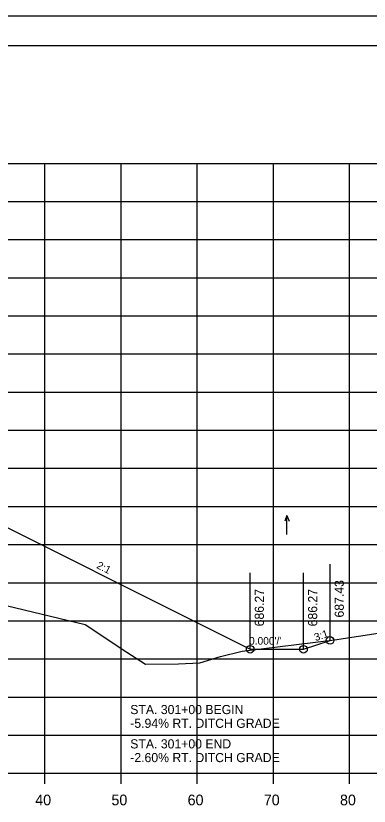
# Model space of a CAD drawing. Extents: x 1370515 to 1370849, y 383299 to 386073.
# Drawn here: x 1370714 to 1370760.4, y 383622.4 to 383726.1 of the extents above; entities that cross this region are included whole.
import ezdxf

# ---------------------------------------------------------------- set-up
doc = ezdxf.new("R2010")
doc.units = 0
for name, color, linetype in [('R_Axis', 7, 'Continuous'), ('R_Axis Annot', 7, 'Continuous'), ('R_Border', 7, 'Continuous'), ('R_Drive', 7, 'Continuous'), ('R_Exist Surface', 7, 'Continuous'), ('R_Fin Surface', 7, 'Continuous'), ('R_Grid', 7, 'Continuous'), ('R_No Plot', 7, 'Continuous'), ('R_Water Annot', 7, 'Continuous'), ('R_Xsect Elev', 7, 'Continuous'), ('R_Xsect Slope', 7, 'Continuous')]:
    doc.layers.add(name, color=color, linetype=linetype)

msp = doc.modelspace()

# ---------------------------------------------------------------- linework, layer by layer
at = {"layer": 'R_Axis'}
for p, q in [((1370717.8, 383625.35), (1370717.8, 383628.15)), ((1370727.8, 383625.35), (1370727.8, 383628.15)), ((1370737.8, 383625.35), (1370737.8, 383628.15)), ((1370747.8, 383625.35), (1370747.8, 383628.15)), ((1370757.8, 383625.35), (1370757.8, 383628.15)), ((1370537.8, 383626.75), (1370817.8, 383626.75))]:
    msp.add_line(p, q, dxfattribs=at)
at = {"layer": 'R_Border'}
msp.add_line((1370527.8, 383722.21), (1370843.98, 383722.21), dxfattribs=at)
at = {"layer": 'R_Exist Surface'}
msp.add_lwpolyline([(1370711.57, 383649.01), (1370723.09, 383646.26), (1370728.57, 383642.65), (1370731, 383641.06), (1370735.36, 383641.12), (1370738.15, 383641.23), (1370740.84, 383642.05), (1370743.68, 383642.77), (1370755.82, 383644.25), (1370774.74, 383647.12), (1370779.58, 383648.74), (1370799.35, 383655.15), (1370805.11, 383657.03), (1370806.63, 383657.52), (1370817.8, 383660.64)], dxfattribs=at)
at = {"layer": 'R_Fin Surface'}
msp.add_lwpolyline([(1370637.35, 383666.9), (1370647.71, 383663.45), (1370651.8, 383664.81), (1370657.8, 383666.31), (1370665.8, 383666.05), (1370677.8, 383665.65), (1370689.8, 383665.26), (1370697.8, 383664.99), (1370703.8, 383663.49), (1370744.75, 383643.02), (1370751.75, 383643.02), (1370755.24, 383644.18)], dxfattribs=at)
at = {"layer": 'R_Grid'}
for p, q in [((1370537.8, 383706.75), (1370817.8, 383706.75)), ((1370717.8, 383626.75), (1370717.8, 383706.75)), ((1370727.8, 383626.75), (1370727.8, 383706.75)), ((1370737.8, 383626.75), (1370737.8, 383706.75)), ((1370747.8, 383626.75), (1370747.8, 383706.75)), ((1370757.8, 383626.75), (1370757.8, 383706.75)), ((1370537.8, 383701.75), (1370817.8, 383701.75)), ((1370537.8, 383696.75), (1370817.8, 383696.75)), ((1370537.8, 383691.75), (1370817.8, 383691.75)), ((1370537.8, 383686.75), (1370817.8, 383686.75)), ((1370537.8, 383681.75), (1370817.8, 383681.75)), ((1370537.8, 383676.75), (1370817.8, 383676.75)), ((1370537.8, 383671.75), (1370817.8, 383671.75)), ((1370537.8, 383666.75), (1370817.8, 383666.75)), ((1370537.8, 383661.75), (1370817.8, 383661.75)), ((1370537.8, 383656.75), (1370817.8, 383656.75)), ((1370537.8, 383651.75), (1370817.8, 383651.75)), ((1370537.8, 383646.75), (1370817.8, 383646.75)), ((1370537.8, 383641.75), (1370817.8, 383641.75)), ((1370537.8, 383636.75), (1370817.8, 383636.75)), ((1370537.8, 383631.75), (1370817.8, 383631.75)), ((1370537.8, 383626.75), (1370817.8, 383626.75))]:
    msp.add_line(p, q, dxfattribs=at)
at = {"layer": 'R_No Plot'}
msp.add_line((1370515.4, 383726.1), (1370848.73, 383726.1), dxfattribs=at)
for points in [[(1370515.39, 383726.1), (1370848.73, 383726.1), (1370848.73, 383512.76), (1370515.39, 383512.76)], [(1370761.72, 383722.21), (1370761.72, 383712.33), (1370797.45, 383712.33), (1370797.45, 383709.41), (1370820.65, 383709.41), (1370820.65, 383686.19), (1370843.98, 383686.19), (1370843.98, 383516.75), (1370527.8, 383516.75), (1370527.8, 383722.21)]]:
    msp.add_lwpolyline(points, close=True, dxfattribs=at)
for centre in [(1370755.24, 383644.18), (1370744.75, 383643.02), (1370744.75, 383643.02), (1370751.75, 383643.02)]:
    msp.add_circle(centre, 0.5, dxfattribs=at)
at = {"layer": 'R_Water Annot'}
for p, q in [((1370749.57, 383660.58), (1370749.29, 383659.81)), ((1370749.57, 383658.06), (1370749.57, 383660.58)), ((1370749.57, 383660.58), (1370749.85, 383659.81))]:
    msp.add_line(p, q, dxfattribs=at)
at = {"layer": 'R_Xsect Elev'}
for p, q in [((1370755.24, 383644.18), (1370755.24, 383654.18)), ((1370744.75, 383643.02), (1370744.75, 383653.02)), ((1370751.75, 383643.02), (1370751.75, 383653.02))]:
    msp.add_line(p, q, dxfattribs=at)

# ---------------------------------------------------------------- texts
at = {"layer": 'R_Axis Annot'}
for s, p in [('40', (1370716.54, 383622.55)), ('50', (1370726.54, 383622.55)), ('60', (1370736.54, 383622.55)), ('70', (1370746.54, 383622.55)), ('80', (1370756.54, 383622.55))]:
    msp.add_text(s, height=1.4, dxfattribs=at).set_placement(p)
at = {"layer": 'R_Drive'}
for s, p in [('STA. 301+00 BEGIN', (1370729.01, 383634.51)), ('-5.94% RT. DITCH GRADE', (1370729.01, 383632.71)), ('STA. 301+00 END', (1370729.01, 383630.01)), ('-2.60% RT. DITCH GRADE', (1370729.01, 383628.21))]:
    msp.add_text(s, height=1.2, dxfattribs=at).set_placement(p)
at = {"layer": 'R_No Plot'}
for p in [(1370723.05, 383646.21), (1370743.63, 383642.72), (1370730.96, 383641.01), (1370738.11, 383641.18)]:
    msp.add_text('+', height=0.1, dxfattribs=at).set_placement(p)
at = {"layer": 'R_Xsect Elev'}
for s, p in [('687.43', (1370757.04, 383647.18)), ('686.27', (1370746.55, 383646.02)), ('686.27', (1370753.55, 383646.02))]:
    msp.add_text(s, height=1.2, rotation=90, dxfattribs=at).set_placement(p)
at = {"layer": 'R_Xsect Slope'}
for s, rotation, p in [('2:1', 333.4349, (1370724.5, 383653.7)), ('3:1', 18.4349, (1370753.34, 383644.07)), ("0.000'/'", 360, (1370744.6, 383643.62))]:
    msp.add_text(s, height=1, rotation=rotation, dxfattribs=at).set_placement(p)

doc.saveas('drawing.dxf')
